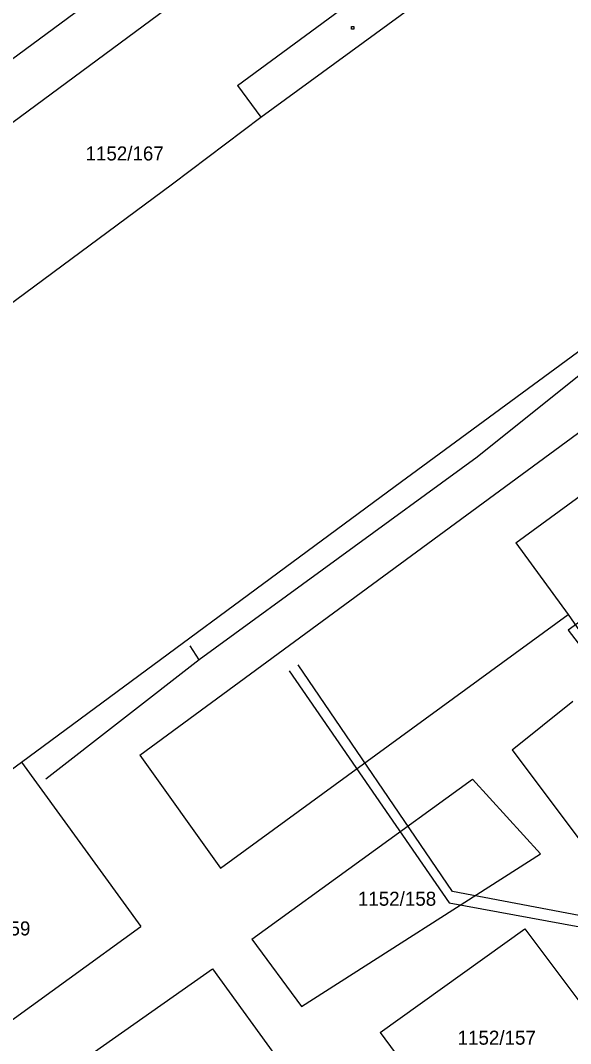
# Model space of a CAD drawing. Extents: x -609709 to -609357, y -1051535 to -1051131.
# Drawn here: x -609637.29 to -609620.63, y -1051331.13 to -1051300.14 of the extents above; entities that cross this region are included whole.
import ezdxf

# ---------------------------------------------------------------- set-up
doc = ezdxf.new("R2010")
doc.units = 0
for name, color, linetype in [('Vrstva 10', 7, 'Continuous'), ('Vrstva 12', 7, 'Continuous'), ('Vrstva 19', 7, 'Continuous')]:
    doc.layers.add(name, color=color, linetype=linetype)

msp = doc.modelspace()

# ---------------------------------------------------------------- linework, layer by layer
at = {"layer": 'Vrstva 10'}
for p, q in [((-609672.03, -1051326.83), (-609621.69, -1051289.57)), ((-609641.4, -1051306.08), (-609629.2, -1051297.06)), ((-609630.01, -1051303.07), (-609623.84, -1051298.56)), ((-609630.72, -1051302.11), (-609627.28, -1051299.58)), ((-609627.265, -1051300.325), (-609627.19, -1051300.325)), ((-609627.265, -1051300.4), (-609627.265, -1051300.325)), ((-609627.19, -1051300.4), (-609627.265, -1051300.4)), ((-609627.19, -1051300.325), (-609627.19, -1051300.4)), ((-609630.72, -1051302.11), (-609630.01, -1051303.07)), ((-609632.69, -1051305.09), (-609630.01, -1051303.07)), ((-609622.29, -1051315.96), (-609605.95, -1051304.07)), ((-609638.34, -1051309.28), (-609632.69, -1051305.09)), ((-609625.94, -1051314.25), (-609614.57, -1051305.87)), ((-609633.67, -1051322.4), (-609613.31, -1051307.42)), ((-609637.26, -1051322.61), (-609625.94, -1051314.25)), ((-609622.29, -1051315.96), (-609620.7, -1051318.14)), ((-609631.23, -1051325.82), (-609620.7, -1051318.14)), ((-609620.7, -1051318.14), (-609619.44, -1051319.97)), ((-609622.4, -1051322.24), (-609620.56, -1051320.76)), ((-609622.4, -1051322.24), (-609616.03, -1051330.75)), ((-609633.67, -1051322.4), (-609631.23, -1051325.82)), ((-609640.41, -1051324.92), (-609637.26, -1051322.61)), ((-609637.26, -1051322.61), (-609633.64, -1051327.59)), ((-609630.28, -1051327.97), (-609623.6, -1051323.13)), ((-609623.6, -1051323.13), (-609621.54, -1051325.39)), ((-609628.78, -1051330.01), (-609621.54, -1051325.39)), ((-609639.92, -1051332.13), (-609633.64, -1051327.59)), ((-609626.4, -1051330.8), (-609622.01, -1051327.66)), ((-609622.01, -1051327.66), (-609619.58, -1051330.92)), ((-609630.28, -1051327.97), (-609628.78, -1051330.01)), ((-609643.62, -1051337.41), (-609631.47, -1051328.87)), ((-609631.47, -1051328.87), (-609625.28, -1051337.44)), ((-609626.4, -1051330.8), (-609623.99, -1051334.02))]:
    msp.add_line(p, q, dxfattribs=at)
at = {"layer": 'Vrstva 12'}
for points in [[(-609644.336, -1051251.436), (-609604.801, -1051307.048), (-609620.698, -1051318.606), (-609619.426, -1051320.272)], [(-609615.16, -1051316.797), (-609615.47, -1051316.4), (-609616.96, -1051313), (-609619.33, -1051311.61), (-609620.02, -1051310.61), (-609623.46, -1051313.37), (-609631.88, -1051319.51), (-609632.148, -1051319.084)], [(-609631.88, -1051319.51), (-609636.52, -1051323.13)]]:
    msp.add_lwpolyline(points, dxfattribs=at)
at = {"layer": 'Vrstva 19'}
for points in [[(-609589.4, -1051320.8), (-609592.21, -1051322.91), (-609598.22, -1051327.36), (-609602.54, -1051330.5), (-609608.92, -1051329.35), (-609617.28, -1051327.84), (-609624.2, -1051326.53), (-609628.88, -1051319.66)], [(-609629.15, -1051319.84), (-609624.31, -1051326.87), (-609617.38, -1051328.14), (-609608.98, -1051329.67), (-609602.4, -1051330.86), (-609598.06, -1051327.65), (-609592.07, -1051323.12), (-609589.26, -1051320.99)]]:
    msp.add_lwpolyline(points, dxfattribs=at)

# ---------------------------------------------------------------- texts
at = {"layer": 'Vrstva 10'}
for s, p in [('1152/167', (-609635.32, -1051304.38)), ('1152/158', (-609627.07, -1051326.96)), ('1152/159', (-609639.36, -1051327.86)), ('1152/157', (-609624.05, -1051331.17))]:
    msp.add_text(s, height=0.425, dxfattribs=at).set_placement(p)

doc.saveas('drawing.dxf')
